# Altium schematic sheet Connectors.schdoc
size 320 x 217 mm
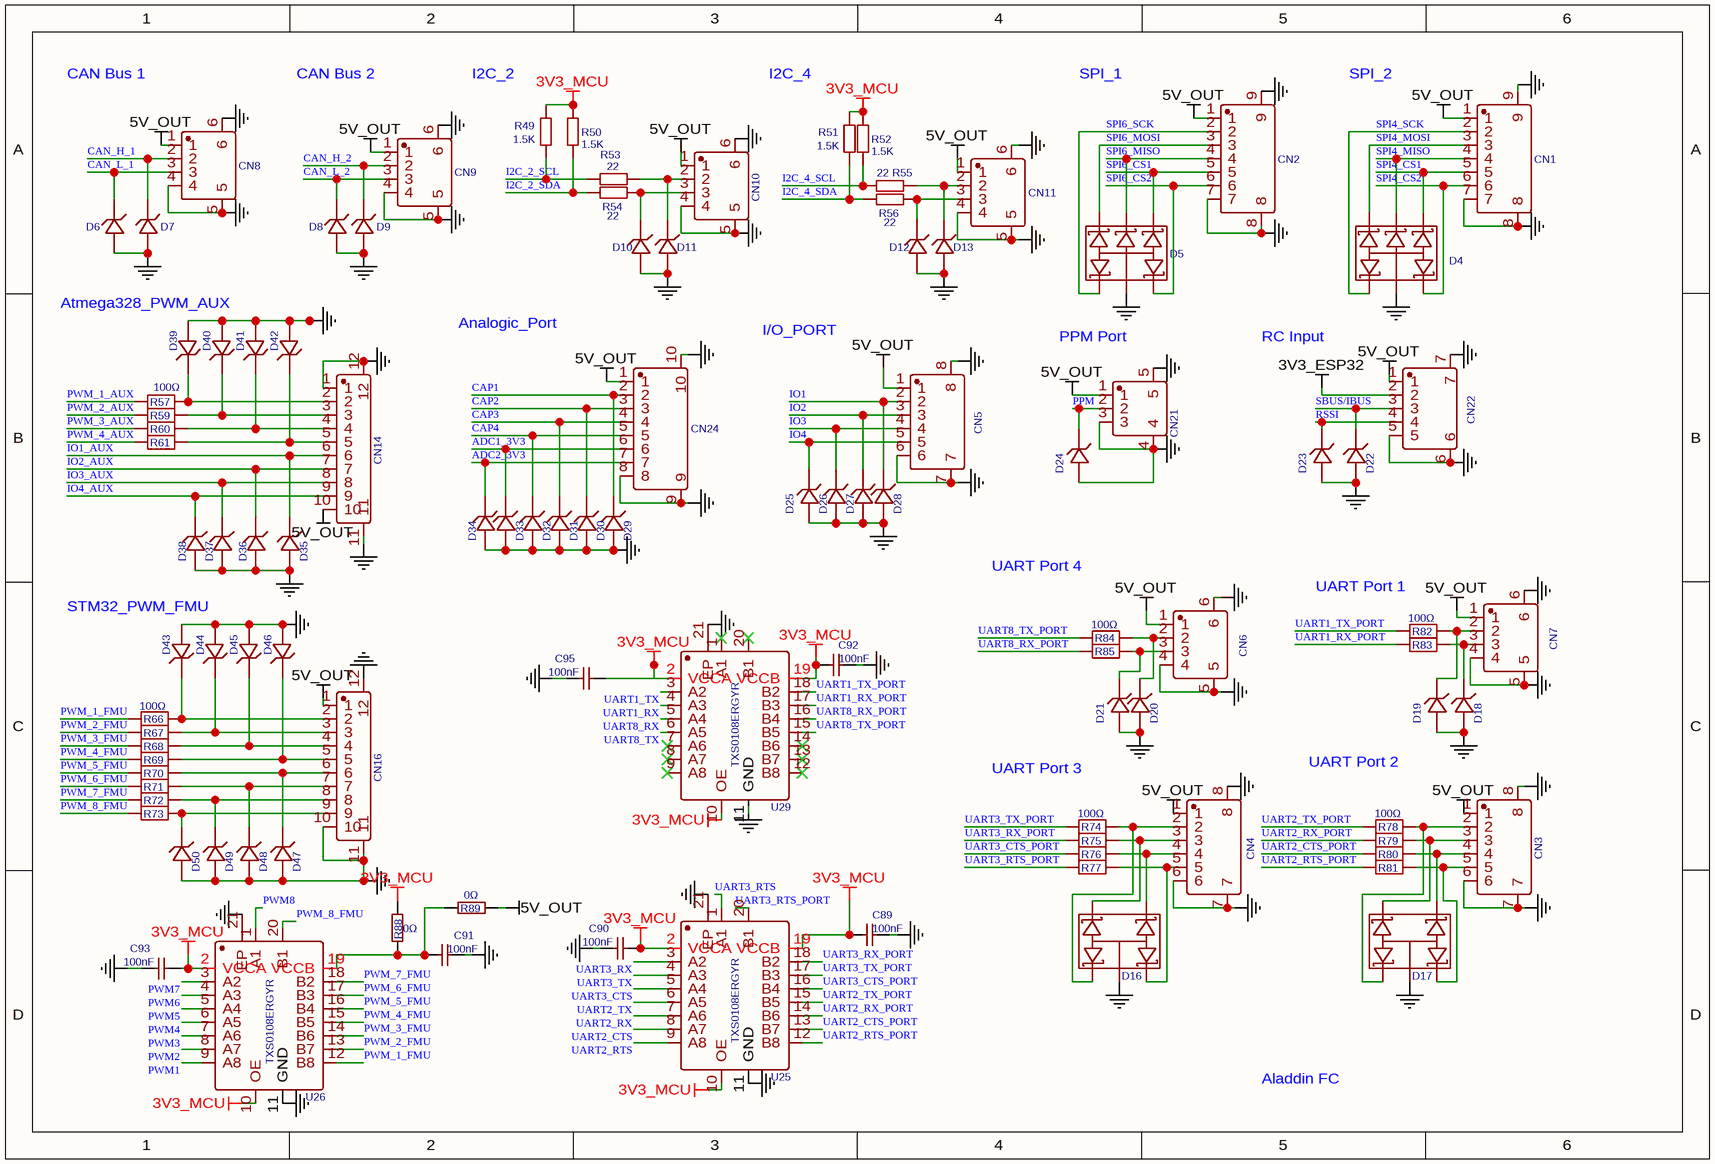
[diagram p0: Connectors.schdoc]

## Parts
C89  100nF  [C0805]
C90  100nF  [C0805]
C91  100nF  [C0805]
C92  100nF  [C0805]
C93  100nF  [C0805]
C95  100nF  [C0805]
CN1  A1257WV-S-7P  [CONN-SMD_A1257WV-S-7P]  (value not drawn)
CN2  A1257WV-S-7P  [CONN-SMD_A1257WV-S-7P]  (value not drawn)
CN3  A1257WV-S-6P  [CONN-SMD_A1257WV-S-6P]  (value not drawn)
CN4  A1257WV-S-6P  [CONN-SMD_A1257WV-S-6P]  (value not drawn)
CN5  A1257WV-S-6P  [CONN-SMD_A1257WV-S-6P]  (value not drawn)
CN6  A1257WV-S-4P  [CONN-SMD_A1257WV-S-4P]  (value not drawn)
CN7  A1257WV-S-4P  [CONN-SMD_A1257WV-S-4P]  (value not drawn)
CN8  A1257WV-S-4P  [CONN-SMD_A1257WV-S-4P]  (value not drawn)
CN9  A1257WV-S-4P  [CONN-SMD_A1257WV-S-4P]  (value not drawn)
CN10  A1257WV-S-4P  [CONN-SMD_A1257WV-S-4P]  (value not drawn)
CN11  A1257WV-S-4P  [CONN-SMD_A1257WV-S-4P]  (value not drawn)
CN14  GH125-S10CCA-00  [CONN-SMD_10P-P1.25_JS_GH125-S10CCA-00]  (value not drawn)
CN16  GH125-S10CCA-00  [CONN-SMD_10P-P1.25_JS_GH125-S10CCA-00]  (value not drawn)
CN21  A1257WR-S-3P  [CONN-SMD_A1257WR-S-3P]  (value not drawn)
CN22  A1257WR-S-5P  [CONN-SMD_A1257WR-S-5P]  (value not drawn)
CN24  A1257WR-S-8P  [CONN-SMD_A1257WR-S-8P]  (value not drawn)
D4  SP1001-05JTG  [SC-70-6_L2.2-W1.3-P0.65-LS2.1-BL]  (value not drawn)
D5  SP1001-05JTG  [SC-70-6_L2.2-W1.3-P0.65-LS2.1-BL]  (value not drawn)
D6  ESD9X5V-2/TR  [FBP-02C_L1.0-W0.6-RD]  (value not drawn)
D7  ESD9X5V-2/TR  [FBP-02C_L1.0-W0.6-RD]  (value not drawn)
D8  ESD9X5V-2/TR  [FBP-02C_L1.0-W0.6-RD]  (value not drawn)
D9  ESD9X5V-2/TR  [FBP-02C_L1.0-W0.6-RD]  (value not drawn)
D10  ESD9X5V-2/TR  [FBP-02C_L1.0-W0.6-RD]  (value not drawn)
D11  ESD9X5V-2/TR  [FBP-02C_L1.0-W0.6-RD]  (value not drawn)
D12  ESD9X5V-2/TR  [FBP-02C_L1.0-W0.6-RD]  (value not drawn)
D13  ESD9X5V-2/TR  [FBP-02C_L1.0-W0.6-RD]  (value not drawn)
D16  SP1001-04JTG  [SC-70-5_L2.1-W1.3-P0.65-LS2.2-BR]  (value not drawn)
D17  SP1001-04JTG  [SC-70-5_L2.1-W1.3-P0.65-LS2.2-BR]  (value not drawn)
D18  ESD9X5V-2/TR  [FBP-02C_L1.0-W0.6-RD]  (value not drawn)
D19  ESD9X5V-2/TR  [FBP-02C_L1.0-W0.6-RD]  (value not drawn)
D20  ESD9X5V-2/TR  [FBP-02C_L1.0-W0.6-RD]  (value not drawn)
D21  ESD9X5V-2/TR  [FBP-02C_L1.0-W0.6-RD]  (value not drawn)
D22  ESD9X5V-2/TR  [FBP-02C_L1.0-W0.6-RD]  (value not drawn)
D23  ESD9X5V-2/TR  [FBP-02C_L1.0-W0.6-RD]  (value not drawn)
D24  ESD9X5V-2/TR  [FBP-02C_L1.0-W0.6-RD]  (value not drawn)
D25  ESD9X5V-2/TR  [FBP-02C_L1.0-W0.6-RD]  (value not drawn)
D26  ESD9X5V-2/TR  [FBP-02C_L1.0-W0.6-RD]  (value not drawn)
D27  ESD9X5V-2/TR  [FBP-02C_L1.0-W0.6-RD]  (value not drawn)
D28  ESD9X5V-2/TR  [FBP-02C_L1.0-W0.6-RD]  (value not drawn)
D29  ESD9X5V-2/TR  [FBP-02C_L1.0-W0.6-RD]  (value not drawn)
D30  ESD9X5V-2/TR  [FBP-02C_L1.0-W0.6-RD]  (value not drawn)
D31  ESD9X5V-2/TR  [FBP-02C_L1.0-W0.6-RD]  (value not drawn)
D32  ESD9X5V-2/TR  [FBP-02C_L1.0-W0.6-RD]  (value not drawn)
D33  ESD9X5V-2/TR  [FBP-02C_L1.0-W0.6-RD]  (value not drawn)
D34  ESD9X5V-2/TR  [FBP-02C_L1.0-W0.6-RD]  (value not drawn)
D35  ESD9X5V-2/TR  [FBP-02C_L1.0-W0.6-RD]  (value not drawn)
D36  ESD9X5V-2/TR  [FBP-02C_L1.0-W0.6-RD]  (value not drawn)
D37  ESD9X5V-2/TR  [FBP-02C_L1.0-W0.6-RD]  (value not drawn)
D38  ESD9X5V-2/TR  [FBP-02C_L1.0-W0.6-RD]  (value not drawn)
D39  ESD9X5V-2/TR  [FBP-02C_L1.0-W0.6-RD]  (value not drawn)
D40  ESD9X5V-2/TR  [FBP-02C_L1.0-W0.6-RD]  (value not drawn)
D41  ESD9X5V-2/TR  [FBP-02C_L1.0-W0.6-RD]  (value not drawn)
D42  ESD9X5V-2/TR  [FBP-02C_L1.0-W0.6-RD]  (value not drawn)
D43  ESD9X5V-2/TR  [FBP-02C_L1.0-W0.6-RD]  (value not drawn)
D44  ESD9X5V-2/TR  [FBP-02C_L1.0-W0.6-RD]  (value not drawn)
D45  ESD9X5V-2/TR  [FBP-02C_L1.0-W0.6-RD]  (value not drawn)
D46  ESD9X5V-2/TR  [FBP-02C_L1.0-W0.6-RD]  (value not drawn)
D47  ESD9X5V-2/TR  [FBP-02C_L1.0-W0.6-RD]  (value not drawn)
D48  ESD9X5V-2/TR  [FBP-02C_L1.0-W0.6-RD]  (value not drawn)
D49  ESD9X5V-2/TR  [FBP-02C_L1.0-W0.6-RD]  (value not drawn)
D50  ESD9X5V-2/TR  [FBP-02C_L1.0-W0.6-RD]  (value not drawn)
R49  1.5K  [R0805]
R50  1.5K  [R0805]
R51  1.5K  [R0805]
R52  1.5K  [R0805]
R53  22  [R0805]
R54  22  [R0805]
R55  22  [R0805]
R56  22  [R0805]
R57  100Ω  [R0603]
R59  100Ω  [R0603]  (value not drawn)
R60  100Ω  [R0603]  (value not drawn)
R61  100Ω  [R0603]  (value not drawn)
R66  100Ω  [R0603]
R67  100Ω  [R0603]  (value not drawn)
R68  100Ω  [R0603]  (value not drawn)
R69  100Ω  [R0603]  (value not drawn)
R70  100Ω  [R0603]  (value not drawn)
R71  100Ω  [R0603]  (value not drawn)
R72  100Ω  [R0603]  (value not drawn)
R73  100Ω  [R0603]  (value not drawn)
R74  100Ω  [R0603]
R75  100Ω  [R0603]  (value not drawn)
R76  100Ω  [R0603]  (value not drawn)
R77  100Ω  [R0603]  (value not drawn)
R78  100Ω  [R0603]
R79  100Ω  [R0603]  (value not drawn)
R80  100Ω  [R0603]  (value not drawn)
R81  100Ω  [R0603]  (value not drawn)
R82  100Ω  [R0603]
R83  100Ω  [R0603]  (value not drawn)
R84  100Ω  [R0603]
R85  100Ω  [R0603]  (value not drawn)
R88  0Ω  [R0805]
R89  0Ω  [R0805]
U25  TXS0108ERGYR  [VQFN-20_L4.6-W3.6-P0.50-BL-EP]
U26  TXS0108ERGYR  [VQFN-20_L4.6-W3.6-P0.50-BL-EP]
U29  TXS0108ERGYR  [VQFN-20_L4.6-W3.6-P0.50-BL-EP]

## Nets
3V3_ESP32: CN22.2
3V3_MCU: C89.2 C90.1 C92.1 C93.1 C95.2 R49.2 R50.2 R51.2 R52.2 R88.2 U25.2(VCCA) U25.10(OE) U25.19(VCCB) U26.2(VCCA) U26.10(OE) U29.2(VCCA) U29.10(OE) U29.19(VCCB)
5V_OUT: CN1.1 CN2.1 CN3.1 CN4.1 CN5.1 CN6.1 CN7.1 CN8.1 CN9.1 CN10.1 CN11.1 CN14.10 CN16.1 CN21.1 CN22.1 CN24.1 R89.1
GND: C89.1 C90.2 C91.1 C92.2 C93.2 C95.1 CN1.7 CN1.8 CN1.9 CN2.7 CN2.8 CN2.9 CN3.6 CN3.7 CN3.8 CN4.6 CN4.7 CN4.8 CN5.6 CN5.7 CN5.8 CN6.4 CN6.5 CN6.6 CN7.4 CN7.5 CN7.6 CN8.4 CN8.5 CN8.6 CN9.4 CN9.5 CN9.6 CN10.4 CN10.5 CN10.6 CN11.4 CN11.5 CN11.6 CN14.1 CN14.11 CN14.12 CN16.10 CN16.11 CN16.12 CN21.3 CN21.4 CN21.5 CN22.5 CN22.6 CN22.7 CN24.8 CN24.9 CN24.10 D4.2 D5.2 D6.2 D7.2 D8.2 D9.2 D10.2 D11.2 D12.2 D13.2 D16.2 D17.2 D18.2 D19.2 D20.2 D21.2 D22.2 D23.2 D24.2 D25.2 D26.2 D27.2 D28.2 D29.2 D30.2 D31.2 D32.2 D33.2 D34.2 D35.2 D36.2 D37.2 D38.2 D39.2 D40.2 D41.2 D42.2 D43.2 D44.2 D45.2 D46.2 D47.2 D48.2 D49.2 D50.2 U25.11(GND) U25.21(EP) U26.11(GND) U26.21(EP) U29.11(GND) U29.21(EP)
ADC1_3V3: CN24.6 D33.1
ADC2_3V3: CN24.7 D34.1
CAN_H_1: CN8.2 D7.1
CAN_H_2: CN9.2 D9.1
CAN_L_1: CN8.3 D6.1
CAN_L_2: CN9.3 D8.1
CAP1: CN24.2 D29.1
CAP2: CN24.3 D30.1
CAP3: CN24.4 D31.1
CAP4: CN24.5 D32.1
I2C_2_SCL: R49.1 R53.1
I2C_2_SDA: R50.1 R54.2
I2C_4_SCL: R52.1 R55.1
I2C_4_SDA: R51.1 R56.1
IO1: CN5.2 D28.1
IO1_AUX: CN14.6 D35.1
IO2: CN5.3 D27.1
IO2_AUX: CN14.7 D36.1
IO3: CN5.4 D26.1
IO3_AUX: CN14.8 D37.1
IO4: CN5.5 D25.1
IO4_AUX: CN14.9 D38.1
PPM: CN21.2 D24.1
PWM1: U26.9(A8)
PWM2: U26.8(A7)
PWM3: U26.7(A6)
PWM4: U26.6(A5)
PWM5: U26.5(A4)
PWM6: U26.4(A3)
PWM7: U26.3(A2)
PWM8: U26.1(A1)
PWM_1_AUX: R57.1
PWM_1_FMU: R66.1 U26.12(B8)
PWM_2_AUX: R59.1
PWM_2_FMU: R67.1 U26.13(B7)
PWM_3_AUX: R60.1
PWM_3_FMU: R68.1 U26.14(B6)
PWM_4_AUX: R61.1
PWM_4_FMU: R69.1 U26.15(B5)
PWM_5_FMU: R70.1 U26.16(B4)
PWM_6_FMU: R71.1 U26.17(B3)
PWM_7_FMU: R72.1 U26.18(B2)
PWM_8_FMU: R73.1 U26.20(B1)
RSSI: CN22.4 D23.1
SBUS/IBUS: CN22.3 D22.1
SPI4_CS1: CN1.5 D4.4
SPI4_CS2: CN1.6 D4.3
SPI4_MISO: CN1.4 D4.5
SPI4_MOSI: CN1.3 D4.6
SPI4_SCK: CN1.2 D4.1
SPI6_CS1: CN2.5 D5.4
SPI6_CS2: CN2.6 D5.3
SPI6_MISO: CN2.4 D5.5
SPI6_MOSI: CN2.3 D5.6
SPI6_SCK: CN2.2 D5.1
UART1_RX: U29.4(A3)
UART1_RX_PORT: R83.1 U29.17(B3)
UART1_TX: U29.3(A2)
UART1_TX_PORT: R82.1 U29.18(B2)
UART2_CTS: U25.8(A7)
UART2_CTS_PORT: R80.1 U25.13(B7)
UART2_RTS: U25.9(A8)
UART2_RTS_PORT: R81.1 U25.12(B8)
UART2_RX: U25.7(A6)
UART2_RX_PORT: R79.1 U25.14(B6)
UART2_TX: U25.6(A5)
UART2_TX_PORT: R78.1 U25.15(B5)
UART3_CTS: U25.5(A4)
UART3_CTS_PORT: R76.1 U25.16(B4)
UART3_RTS: U25.1(A1)
UART3_RTS_PORT: R77.1 U25.20(B1)
UART3_RX: U25.3(A2)
UART3_RX_PORT: R75.1 U25.18(B2)
UART3_TX: U25.4(A3)
UART3_TX_PORT: R74.1 U25.17(B3)
UART8_RX: U29.5(A4)
UART8_RX_PORT: R85.1 U29.16(B4)
UART8_TX: U29.6(A5)
UART8_TX_PORT: R84.1 U29.15(B5)
NetC91_2: C91.2 R88.1 R89.2 U26.19(VCCB)
NetCN3_2: CN3.2 D17.1 R78.2
NetCN3_3: CN3.3 D17.5 R79.2
NetCN3_4: CN3.4 D17.4 R80.2
NetCN3_5: CN3.5 D17.3 R81.2
NetCN4_2: CN4.2 D16.1 R74.2
NetCN4_3: CN4.3 D16.5 R75.2
NetCN4_4: CN4.4 D16.4 R76.2
NetCN4_5: CN4.5 D16.3 R77.2
NetCN6_2: CN6.2 D20.1 R84.2
NetCN6_3: CN6.3 D21.1 R85.2
NetCN7_2: CN7.2 D19.1 R82.2
NetCN7_3: CN7.3 D18.1 R83.2
NetCN10_2: CN10.2 D11.1 R53.2
NetCN10_3: CN10.3 D10.1 R54.1
NetCN11_2: CN11.2 D13.1 R55.2
NetCN11_3: CN11.3 D12.1 R56.2
NetCN14_2: CN14.2 D39.1 R57.2
NetCN14_3: CN14.3 D40.1 R59.2
NetCN14_4: CN14.4 D41.1 R60.2
NetCN14_5: CN14.5 D42.1 R61.2
NetCN16_2: CN16.2 D43.1 R66.2
NetCN16_3: CN16.3 D44.1 R67.2
NetCN16_4: CN16.4 D45.1 R68.2
NetCN16_5: CN16.5 D46.1 R69.2
NetCN16_6: CN16.6 D47.1 R70.2
NetCN16_7: CN16.7 D48.1 R71.2
NetCN16_8: CN16.8 D49.1 R72.2
NetCN16_9: CN16.9 D50.1 R73.2

Not connected (* = marked no-connect by the designer): U29 1(A1)* 7(A6)* 8(A7)* 9(A8)* 12(B8)* 13(B7)* 14(B6)* 20(B1)*

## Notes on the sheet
- CAN Bus 1
- CAN Bus 2
- I2C_2
- I2C_4
- SPI_1
- SPI_2
- (near D39) Atmega328_PWM_AUX
- Analogic_Port
- I/O_PORT
- PPM Port
- RC Input
- UART Port 4
- (near D43) STM32_PWM_FMU
- UART Port 1
- UART Port 3
- UART Port 2
- Aladdin FC

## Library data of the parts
C89-C93 C95 = 100nF: BOM_Manufacturer Part: CL21B104KBCNNNC; BOM_Manufacturer: SAMSUNG; nameAlias: Capacitance
CN1 CN2 = A1257WV-S-7P: BOM_Manufacturer: Changjiang Connectors; Contributor: LCSC
CN3-CN5 = A1257WV-S-6P: BOM_Manufacturer: CJT(长江连接器); Contributor: LCSC
CN6-CN11 = A1257WV-S-4P: BOM_Manufacturer: CJT(长江连接器); Contributor: LCSC
CN14 CN16 = GH125-S10CCA-00: BOM_Manufacturer: JS(钜硕电子); Contributor: LCSC
CN21 = A1257WR-S-3P: BOM_Manufacturer: Changjiang Connectors; Contributor: LCSC
CN22 = A1257WR-S-5P: BOM_Manufacturer: Changjiang Connectors; Contributor: LCSC
CN24 = A1257WR-S-8P: BOM_Manufacturer: CJT(长江连接器); Contributor: LCSC
D4 D5 = SP1001-05JTG: BOM_Manufacturer: Littelfuse; Contributor: LCSC
D6-D13 D18-D50 = ESD9X5V-2/TR: BOM_Manufacturer: Will Semicon; Contributor: LCSC
D16 D17 = SP1001-04JTG: BOM_Manufacturer: Littelfuse; Contributor: LCSC
R49-R52 = 1.5K: BOM_Manufacturer: BOURNS; BOM_Manufacturer Part: CR0805-FX-1501ELF; nameAlias: Resistance (Ohms); Contributor: LCSC; Resistance: 1.5kΩ
R53-R56 = 22: BOM_Manufacturer: BOURNS; BOM_Manufacturer Part: CR0805-FX-22R0ELF; nameAlias: Resistance (Ohms); Contributor: LCSC; Resistance: 22Ω
R57 R59-R61 R66-R85 = 100Ω: BOM_Manufacturer: FOJAN(富捷); BOM_Manufacturer Part: FRC0603J101 TS; nameAlias: Resistance; Contributor: lcsc
R88 R89 = 0Ω: BOM_Manufacturer: UniOhm; BOM_Manufacturer Part: 0805W8F0000T5E; nameAlias: Resistance; Resistance (Ohms): 0
U25 U26 U29 = TXS0108ERGYR: BOM_Manufacturer: TI(德州仪器); Contributor: LCSC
